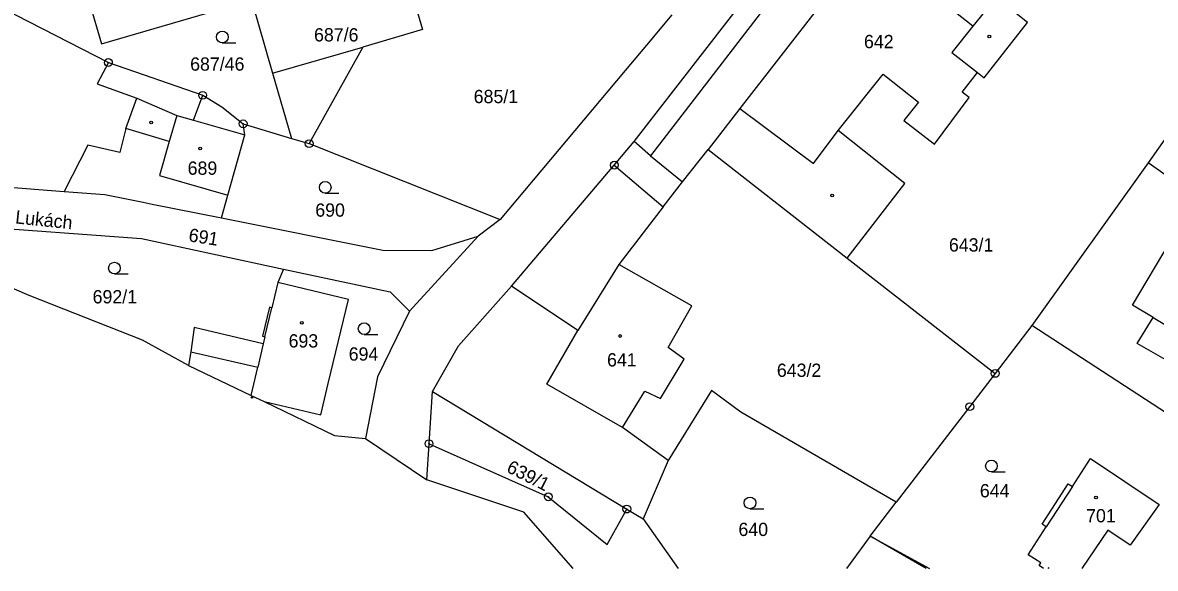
# Model space of a CAD drawing. Extents: x -749778 to -749372, y -967291 to -966955.
# Drawn here: x -749652.7 to -749507.7, y -967290.9 to -967221.1 of the extents above; entities that cross this region are included whole.
import ezdxf

# ---------------------------------------------------------------- set-up
doc = ezdxf.new("R2010")
doc.units = 0
for name, color, linetype in [('Hranice parcel', 7, 'Continuous'), ('Parcelní čísla', 7, 'Continuous'), ('Pop  PČ popisy', 7, 'Continuous'), ('Vnitřní kresba', 7, 'Continuous'), ('Značky bodu BP', 7, 'Continuous'), ('Značky budov', 7, 'Continuous'), ('Značky kultur', 7, 'Continuous')]:
    doc.layers.add(name, color=color, linetype=linetype)

msp = doc.modelspace()

# ---------------------------------------------------------------- linework, layer by layer
at = {"layer": 'Hranice parcel'}
for p, q in [((-749496.94, -967222.41), (-749508.59, -967238.99)), ((-749624.5, -967234), (-749618.3, -967235.87)), ((-749618.3, -967235.87), (-749616.05, -967236.54)), ((-749616.05, -967236.54), (-749591.58, -967246.27)), ((-749564.94, -967237.28), (-749547.13, -967251.19)), ((-749590.12, -967254.8), (-749576.96, -967239.3)), ((-749508.59, -967238.99), (-749523.47, -967259.85)), ((-749482.77, -967257.42), (-749508.59, -967238.99)), ((-749591.58, -967246.27), (-749594.41, -967248.4)), ((-749594.41, -967248.4), (-749603.21, -967257.98)), ((-749547.13, -967251.19), (-749528.17, -967265.97)), ((-749651.9, -967256), (-749659.97, -967252.54)), ((-749619.32, -967252.61), (-749620.08, -967254.33)), ((-749581.64, -967260.48), (-749590.12, -967254.8)), ((-749523.47, -967259.85), (-749528.17, -967265.97)), ((-749497.96, -967276.47), (-749523.47, -967259.85)), ((-749631.48, -967264.96), (-749623.47, -967268.79)), ((-749623.47, -967268.79), (-749621.83, -967269.58)), ((-749600.69, -967274.97), (-749600.25, -967268.28)), ((-749600.25, -967268.28), (-749575.36, -967283.34)), ((-749608.83, -967274.3), (-749600.99, -967279.59)), ((-749600.99, -967279.59), (-749600.69, -967274.97)), ((-749588.54, -967283.73), (-749600.99, -967279.59)), ((-749544.18, -967286.81), (-749540.84, -967282.47)), ((-749582.22, -967290.93), (-749588.54, -967283.73)), ((-749537.01, -967290.93), (-749544.18, -967286.81))]:
    msp.add_line(p, q, dxfattribs=at)
for points in [[(-749576.96, -967239.3), (-749574.4, -967236.29), (-749544.44, -967197.63)], [(-749647.62, -967206.72), (-749642.66, -967223.76), (-749623.45, -967218.17)], [(-749547.13, -967251.19), (-749539.73, -967241.65), (-749548.27, -967234.85), (-749542.52, -967227.63), (-749538.01, -967231.22), (-749539.89, -967233.59), (-749535.96, -967236.61), (-749531.53, -967230.62), (-749532.42, -967229.96), (-749530.45, -967227.43), (-749529.58, -967228.12), (-749524.04, -967221.02), (-749528.05, -967217.79), (-749531.02, -967221.51), (-749535.46, -967217.96), (-749532.69, -967214.65), (-749541.02, -967208.23), (-749541.86, -967207.58), (-749546.28, -967213.26), (-749549.5, -967217.04), (-749550.38, -967218.55), (-749560.87, -967232.04), (-749564.94, -967237.28)], [(-749604.25, -967212.58), (-749601.52, -967221.94), (-749609.19, -967224.17), (-749616.05, -967236.54)], [(-749662.69, -967215.35), (-749653.68, -967220.04), (-749641.76, -967226.16), (-749629.68, -967230.35), (-749627.23, -967231.85), (-749624.5, -967234)], [(-749623.45, -967218.17), (-749620.73, -967227.53), (-749618.3, -967235.87)], [(-749569.6, -967220.07), (-749572.84, -967223.93), (-749575.56, -967227.17), (-749591.58, -967246.27)], [(-749627.26, -967246.06), (-749626.47, -967243.14), (-749624.3, -967235.42), (-749624.5, -967234)], [(-749576.96, -967239.3), (-749570.69, -967244.62), (-749568.23, -967241.45), (-749564.94, -967237.28)], [(-749656.66, -967241.94), (-749647.41, -967242.66), (-749642.21, -967243.07), (-749637.32, -967244.05), (-749636.15, -967244.28), (-749627.26, -967246.06)], [(-749659.64, -967247.08), (-749637.51, -967248.69), (-749619.32, -967252.61)], [(-749627.26, -967246.06), (-749606.63, -967250.18), (-749600.32, -967250.23), (-749594.41, -967248.4)], [(-749502.2, -967262.31), (-749504.3, -967265.4), (-749509.97, -967262.12), (-749507.96, -967258.81), (-749510.57, -967257.23), (-749505.77, -967249.11), (-749500.07, -967252.48), (-749496.82, -967254.4), (-749498.4, -967256.85), (-749501.99, -967262.43), (-749502.2, -967262.31)], [(-749619.32, -967252.61), (-749605.66, -967255.54), (-749603.21, -967257.98)], [(-749575.91, -967272.89), (-749573.07, -967268.26), (-749571.05, -967269.17), (-749568.01, -967264.13), (-749570.08, -967262.66), (-749567.04, -967257.33), (-749576.4, -967252), (-749581.64, -967260.48)], [(-749620.08, -967254.33), (-749620.84, -967257.56), (-749621.13, -967257.49), (-749622.01, -967261.21), (-749621.71, -967261.28), (-749621.92, -967262.16), (-749630.77, -967260.11), (-749631.22, -967263.19), (-749631.48, -967264.96)], [(-749621.83, -967269.58), (-749614.55, -967271.26), (-749613.61, -967267.26), (-749611, -967256.52), (-749620.08, -967254.33)], [(-749600.25, -967268.28), (-749596.92, -967262.44), (-749590.12, -967254.8)], [(-749631.48, -967264.96), (-749637.4, -967261.7), (-749651.9, -967256)], [(-749603.21, -967257.98), (-749607.3, -967266.39), (-749608.83, -967274.3)], [(-749575.91, -967272.89), (-749585.62, -967267.34), (-749581.64, -967260.48)], [(-749528.17, -967265.97), (-749531.43, -967270.22), (-749540.84, -967282.47)], [(-749540.84, -967282.47), (-749560.74, -967270.93), (-749564.5, -967268.16), (-749570.05, -967277.11), (-749575.91, -967272.89)], [(-749621.83, -967269.58), (-749612.8, -967273.9), (-749608.83, -967274.3)], [(-749600.69, -967274.97), (-749585.42, -967281.77), (-749577.86, -967287.89), (-749575.36, -967283.34)], [(-749522, -967290.93), (-749522.55, -967290.57), (-749522.33, -967290.24), (-749523.97, -967289.18), (-749521.64, -967285.6), (-749522.14, -967285.27), (-749518.83, -967280.09), (-749518.29, -967280.44), (-749515.96, -967276.86), (-749507.18, -967282.74), (-749510.88, -967287.97), (-749513.74, -967286.03)], [(-749575.36, -967283.34), (-749573.28, -967284.6), (-749568.77, -967290.93)], [(-749513.74, -967286.03), (-749517.06, -967290.93)], [(-749544.18, -967286.81), (-749547.22, -967290.93)], [(-749521.28, -967290.93), (-749521.37, -967290.87), (-749521.41, -967290.93)]]:
    msp.add_lwpolyline(points, dxfattribs=at)
at = {"layer": 'Vnitřní kresba'}
for p, q in [((-749554.64, -967215.12), (-749572.33, -967238.1)), ((-749531.02, -967221.51), (-749533.72, -967224.88)), ((-749620.73, -967227.53), (-749609.19, -967224.17)), ((-749533.72, -967224.88), (-749530.45, -967227.43)), ((-749641.76, -967226.16), (-749643.2, -967228.88)), ((-749643.2, -967228.88), (-749638.11, -967230.71)), ((-749639.51, -967234.62), (-749638.11, -967230.71)), ((-749638.11, -967230.71), (-749633, -967232.93)), ((-749630.87, -967233.55), (-749629.68, -967230.35)), ((-749560.87, -967232.04), (-749551.44, -967239.1)), ((-749633, -967232.93), (-749633.97, -967236.27)), ((-749633, -967232.93), (-749630.87, -967233.55)), ((-749630.87, -967233.55), (-749624.3, -967235.42)), ((-749639.51, -967234.62), (-749640.28, -967237.69)), ((-749633.97, -967236.27), (-749639.51, -967234.62)), ((-749551.44, -967239.1), (-749548.27, -967234.85)), ((-749644.41, -967236.75), (-749647.41, -967242.66)), ((-749640.28, -967237.69), (-749644.41, -967236.75)), ((-749633.97, -967236.27), (-749635.23, -967240.63)), ((-749572.33, -967238.1), (-749574.4, -967236.29)), ((-749572.33, -967238.1), (-749568.23, -967241.45)), ((-749635.23, -967240.63), (-749626.47, -967243.14)), ((-749570.69, -967244.62), (-749576.4, -967252)), ((-749621.71, -967261.28), (-749620.84, -967257.56)), ((-749507.96, -967258.81), (-749502.2, -967262.31)), ((-749621.92, -967262.16), (-749622.62, -967265.15)), ((-749631.22, -967263.19), (-749622.62, -967265.15)), ((-749623.47, -967268.79), (-749622.62, -967265.15)), ((-749570.05, -967277.11), (-749573.28, -967284.6)), ((-749518.29, -967280.44), (-749521.64, -967285.6)), ((-749544.18, -967286.81), (-749536.6, -967290.93))]:
    msp.add_line(p, q, dxfattribs=at)
at = {"layer": 'Značky bodu BP'}
for centre, radius in [((-749641.76, -967226.16), 0.5), ((-749641.76, -967226.16), 0.0303), ((-749629.68, -967230.35), 0.5), ((-749629.68, -967230.35), 0.0303), ((-749624.5, -967234), 0.5), ((-749624.5, -967234), 0.0303), ((-749616.05, -967236.54), 0.5), ((-749616.05, -967236.54), 0.0303), ((-749576.96, -967239.3), 0.5), ((-749576.96, -967239.3), 0.0303), ((-749528.17, -967265.97), 0.5), ((-749528.17, -967265.97), 0.0303), ((-749531.43, -967270.22), 0.5), ((-749531.43, -967270.22), 0.0303), ((-749600.69, -967274.97), 0.5), ((-749600.69, -967274.97), 0.0303), ((-749585.42, -967281.77), 0.5), ((-749585.42, -967281.77), 0.0303), ((-749575.36, -967283.34), 0.5), ((-749575.36, -967283.34), 0.0303)]:
    msp.add_circle(centre, radius, dxfattribs=at)
at = {"layer": 'Značky budov'}
for centre, radius in [((-749528.93, -967222.82), 0.175), ((-749636.28, -967233.83), 0.175), ((-749630.02, -967237.15), 0.175), ((-749549.04, -967243.17), 0.175), ((-749617, -967259.5), 0.175), ((-749576.21, -967261.18), 0.175), ((-749623.37, -967269.04), 0.117), ((-749515.26, -967281.87), 0.175)]:
    msp.add_circle(centre, radius, dxfattribs=at)
at = {"layer": 'Značky kultur'}
for p, q in [((-749627.17, -967223.64), (-749625.42, -967223.64)), ((-749613.99, -967242.89), (-749612.24, -967242.89)), ((-749640.99, -967253.23), (-749639.24, -967253.23)), ((-749609, -967260.99), (-749607.25, -967260.99)), ((-749528.66, -967278.57), (-749526.91, -967278.57)), ((-749559.58, -967283.3), (-749557.83, -967283.3))]:
    msp.add_line(p, q, dxfattribs=at)
for centre in [(-749627.17, -967222.89), (-749613.99, -967242.14), (-749640.99, -967252.48), (-749609, -967260.24), (-749528.66, -967277.82), (-749559.58, -967282.55)]:
    msp.add_circle(centre, 0.75, dxfattribs=at)

# ---------------------------------------------------------------- texts
at = {"layer": 'Parcelní čísla'}
for s, p in [('687/6', (-749615.42, -967223.46)), ('642', (-749544.98, -967224.32)), ('687/46', (-749631.29, -967227.2)), ('685/1', (-749594.97, -967231.36)), ('689', (-749631.61, -967240.53)), ('690', (-749615.26, -967245.9)), ('643/1', (-749534.1, -967250.36)), ('692/1', (-749643.78, -967257)), ('693', (-749618.68, -967262.65)), ('694', (-749610.98, -967264.33)), ('641', (-749577.89, -967265.08)), ('643/2', (-749556.14, -967266.41)), ('644', (-749530.14, -967281.84)), ('701', (-749516.53, -967285.04)), ('640', (-749561.06, -967286.79))]:
    msp.add_text(s, height=1.7, dxfattribs=at).set_placement(p)
for s, rotation, p in [('691', 351, (-749631.57, -967249.04)), ('639/1', 333, (-749590.89, -967278.51))]:
    msp.add_text(s, height=1.7, rotation=rotation, dxfattribs=at).set_placement(p)
at = {"layer": 'Pop  PČ popisy'}
msp.add_text('V Lukách', height=1.7, rotation=354, dxfattribs=at).set_placement((-749655.88, -967246.53))

doc.saveas('drawing.dxf')
